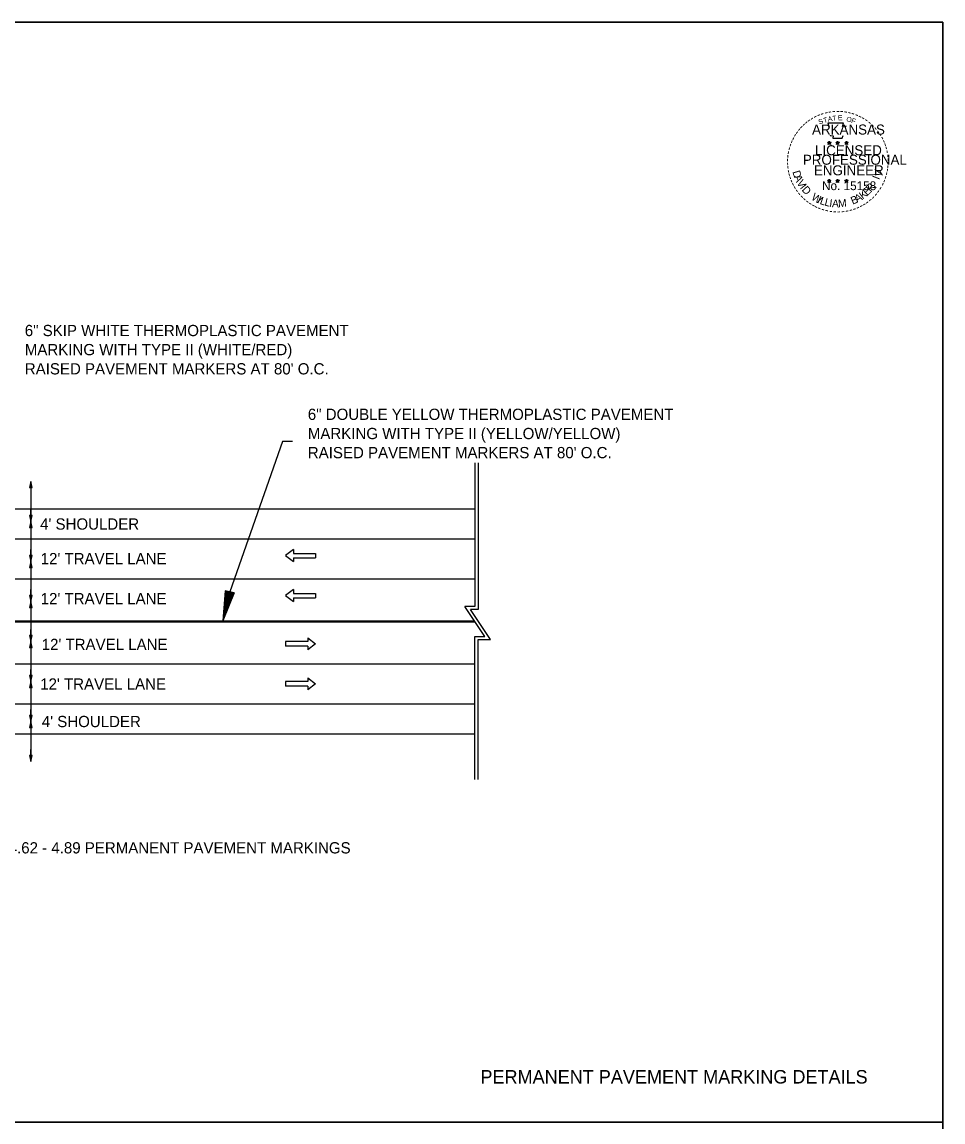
# Model space of a CAD drawing. Extents: x 1372926 to 1373096, y 381240 to 381790.
# Drawn here: x 1373003.9 to 1373096, y 381570.2 to 381680.2 of the extents above; entities that cross this region are included whole.
import ezdxf

# ---------------------------------------------------------------- set-up
doc = ezdxf.new("R2010")
doc.units = 0
for name, color, linetype in [('Default', 7, 'Continuous'), ('DSN_DRFT_Junk-No-Plot', 7, 'Continuous'), ('R_Border Notes', 7, 'Continuous'), ('R_Draft', 7, 'Continuous'), ('SHET_Border-Text', 7, 'Continuous')]:
    doc.layers.add(name, color=color, linetype=linetype)

msp = doc.modelspace()

# ---------------------------------------------------------------- linework, layer by layer
at = {"layer": 'Default'}
for p, q in [((1373029.94, 381638.21), (1373024.65, 381623.19)), ((1373030.94, 381638.21), (1373029.94, 381638.21)), ((1373049.17, 381636.08), (1373049.17, 381621.74)), ((1373049.5, 381636.08), (1373049.5, 381621.41)), ((1373031.02, 381627.41), (1373030.24, 381626.81)), ((1373031.02, 381627.41), (1373031.02, 381627.04)), ((1373030.24, 381626.81), (1373031.02, 381626.21)), ((1373031.02, 381627.04), (1373033.23, 381627.04)), ((1373031.02, 381626.59), (1373033.23, 381626.59)), ((1373031.02, 381626.59), (1373031.02, 381626.21)), ((1373033.23, 381627.04), (1373033.23, 381626.59)), ((1373024.21, 381623.3), (1373023.95, 381620.28)), ((1373025.09, 381623.09), (1373023.95, 381620.28)), ((1373024.29, 381623.28), (1373024.06, 381620.77)), ((1373025.01, 381623.11), (1373024.06, 381620.77)), ((1373024.36, 381623.26), (1373024.18, 381621.27)), ((1373024.94, 381623.12), (1373024.18, 381621.27)), ((1373025.09, 381623.09), (1373024.21, 381623.3)), ((1373024.43, 381623.25), (1373024.3, 381621.75)), ((1373024.87, 381623.14), (1373024.3, 381621.75)), ((1373024.51, 381623.23), (1373024.42, 381622.25)), ((1373024.79, 381623.16), (1373024.42, 381622.25)), ((1373024.58, 381623.21), (1373024.54, 381622.73)), ((1373024.72, 381623.18), (1373024.54, 381622.73)), ((1373031.02, 381623.41), (1373030.24, 381622.81)), ((1373031.02, 381623.41), (1373031.02, 381623.04)), ((1373031.02, 381623.04), (1373033.23, 381623.04)), ((1373033.23, 381623.04), (1373033.23, 381622.59)), ((1373030.24, 381622.81), (1373031.02, 381622.21)), ((1373031.02, 381622.59), (1373033.23, 381622.59)), ((1373031.02, 381622.59), (1373031.02, 381622.21)), ((1373049.17, 381621.74), (1373048.17, 381621.74)), ((1373050.17, 381618.74), (1373048.17, 381621.74)), ((1373050.72, 381618.41), (1373048.72, 381621.41)), ((1373049.5, 381621.41), (1373048.72, 381621.41)), ((1373049.17, 381604.41), (1373049.17, 381618.74)), ((1373049.17, 381618.74), (1373050.17, 381618.74)), ((1373032.45, 381618.22), (1373030.24, 381618.22)), ((1373030.24, 381618.22), (1373030.24, 381617.77)), ((1373032.45, 381617.77), (1373030.24, 381617.77)), ((1373032.45, 381618.59), (1373032.45, 381618.22)), ((1373032.45, 381618.59), (1373033.23, 381617.99)), ((1373033.23, 381617.99), (1373032.45, 381617.39)), ((1373032.45, 381617.77), (1373032.45, 381617.39)), ((1373049.5, 381604.41), (1373049.5, 381618.41)), ((1373049.5, 381618.41), (1373050.72, 381618.41)), ((1373032.45, 381614.22), (1373030.24, 381614.22)), ((1373030.24, 381614.22), (1373030.24, 381613.77)), ((1373032.45, 381614.59), (1373032.45, 381614.22)), ((1373032.45, 381614.59), (1373033.23, 381613.99)), ((1373032.45, 381613.77), (1373030.24, 381613.77)), ((1373033.23, 381613.99), (1373032.45, 381613.39)), ((1373032.45, 381613.77), (1373032.45, 381613.39))]:
    msp.add_line(p, q, dxfattribs=at)
for points in [[(1372925.97, 381680.17), (1372925.97, 381570.17), (1373095.97, 381570.17), (1373095.97, 381680.17)], [(1372925.97, 381570.17), (1372925.97, 381460.17), (1373095.97, 381460.17), (1373095.97, 381570.17)]]:
    msp.add_lwpolyline(points, close=True, dxfattribs=at)
at = {"layer": 'DSN_DRFT_Junk-No-Plot'}
msp.add_line((1373004.76, 381634.24), (1373004.76, 381606.24), dxfattribs=at)
for points in [[(1372925.97, 381680.17), (1373095.97, 381680.17), (1373095.97, 381570.17), (1372925.97, 381570.17)], [(1372925.97, 381680.17), (1372925.97, 381570.17), (1373095.97, 381570.17), (1373095.97, 381680.17)], [(1372925.97, 381570.17), (1373095.97, 381570.17), (1373095.97, 381460.17), (1372925.97, 381460.17)], [(1372925.97, 381570.17), (1372925.97, 381460.17), (1373095.97, 381460.17), (1373095.97, 381570.17)]]:
    msp.add_lwpolyline(points, close=True, dxfattribs=at)
for points in [[(1373004.76, 381634.24), (1373004.64, 381633.64), (1373004.88, 381633.64), (1373004.76, 381634.24), (1373004.76, 381633.04)], [(1373004.76, 381630.24), (1373004.88, 381630.84), (1373004.64, 381630.84), (1373004.76, 381630.24), (1373004.76, 381631.44)], [(1373004.76, 381630.24), (1373004.64, 381629.64), (1373004.88, 381629.64), (1373004.76, 381630.24), (1373004.76, 381629.04)], [(1373004.76, 381626.24), (1373004.88, 381626.84), (1373004.64, 381626.84), (1373004.76, 381626.24), (1373004.76, 381627.44)], [(1373004.76, 381626.24), (1373004.64, 381625.64), (1373004.88, 381625.64), (1373004.76, 381626.24), (1373004.76, 381625.04)], [(1373004.76, 381622.24), (1373004.88, 381622.84), (1373004.64, 381622.84), (1373004.76, 381622.24), (1373004.76, 381623.44)], [(1373004.76, 381622.24), (1373004.64, 381621.64), (1373004.88, 381621.64), (1373004.76, 381622.24), (1373004.76, 381621.04)], [(1373004.76, 381618.24), (1373004.88, 381618.84), (1373004.64, 381618.84), (1373004.76, 381618.24), (1373004.76, 381619.44)], [(1373004.76, 381618.24), (1373004.64, 381617.64), (1373004.88, 381617.64), (1373004.76, 381618.24), (1373004.76, 381617.04)], [(1373004.76, 381614.24), (1373004.88, 381614.84), (1373004.64, 381614.84), (1373004.76, 381614.24), (1373004.76, 381615.44)], [(1373004.76, 381614.24), (1373004.64, 381613.64), (1373004.88, 381613.64), (1373004.76, 381614.24), (1373004.76, 381613.04)], [(1373004.76, 381610.24), (1373004.88, 381610.84), (1373004.64, 381610.84), (1373004.76, 381610.24), (1373004.76, 381611.44)], [(1373004.76, 381610.24), (1373004.64, 381609.64), (1373004.88, 381609.64), (1373004.76, 381610.24), (1373004.76, 381609.04)], [(1373004.76, 381606.24), (1373004.88, 381606.84), (1373004.64, 381606.84), (1373004.76, 381606.24), (1373004.76, 381607.44)]]:
    msp.add_lwpolyline(points, dxfattribs=at)
at = {"layer": 'R_Draft'}
for p, q in [((1372972.78, 381631.49), (1373049.17, 381631.49)), ((1372972.78, 381628.49), (1373049.17, 381628.49)), ((1372972.78, 381624.49), (1373049.17, 381624.49)), ((1372972.74, 381620.29), (1373049.14, 381620.29)), ((1372972.81, 381620.19), (1373049.2, 381620.19)), ((1372972.78, 381615.99), (1373049.17, 381615.99)), ((1372972.78, 381611.99), (1373049.17, 381611.99)), ((1372972.78, 381608.99), (1373049.17, 381608.99))]:
    msp.add_line(p, q, dxfattribs=at)
at = {"layer": 'SHET_Border-Text'}
for p, q in [((1373084.43, 381668.13), (1373084.6, 381668.07)), ((1373084.43, 381668.13), (1373084.56, 381668.11)), ((1373084.43, 381668.13), (1373084.55, 381668.07)), ((1373084.6, 381668.26), (1373084.58, 381668.13)), ((1373084.6, 381668.07), (1373084.6, 381668.26)), ((1373084.6, 381668.26), (1373084.63, 381668.13)), ((1373084.78, 381668.13), (1373084.6, 381668.07)), ((1373084.78, 381668.13), (1373084.63, 381668.11)), ((1373084.78, 381668.13), (1373084.67, 381668.08)), ((1373085.26, 381668.13), (1373085.44, 381668.07)), ((1373085.26, 381668.13), (1373085.39, 381668.11)), ((1373085.26, 381668.13), (1373085.38, 381668.07)), ((1373085.44, 381668.26), (1373085.42, 381668.13)), ((1373085.44, 381668.07), (1373085.44, 381668.26)), ((1373085.44, 381668.26), (1373085.46, 381668.13)), ((1373085.61, 381668.13), (1373085.44, 381668.07)), ((1373085.61, 381668.13), (1373085.47, 381668.11)), ((1373085.61, 381668.13), (1373085.51, 381668.08)), ((1373086.15, 381668.12), (1373086.32, 381668.07)), ((1373086.15, 381668.12), (1373086.27, 381668.1)), ((1373086.15, 381668.12), (1373086.26, 381668.06)), ((1373086.32, 381668.25), (1373086.3, 381668.12)), ((1373086.32, 381668.07), (1373086.32, 381668.25)), ((1373086.32, 381668.25), (1373086.34, 381668.13)), ((1373086.49, 381668.12), (1373086.32, 381668.07)), ((1373086.49, 381668.12), (1373086.35, 381668.1)), ((1373086.49, 381668.12), (1373086.39, 381668.07)), ((1373084.5, 381667.93), (1373084.6, 381668.07)), ((1373084.5, 381667.93), (1373084.56, 381668.05)), ((1373084.5, 381667.93), (1373084.6, 381668.03)), ((1373084.71, 381667.93), (1373084.6, 381668.07)), ((1373084.71, 381667.93), (1373084.6, 381668.03)), ((1373084.71, 381667.93), (1373084.64, 381668.07)), ((1373085.33, 381667.93), (1373085.44, 381668.07)), ((1373085.33, 381667.93), (1373085.39, 381668.05)), ((1373085.33, 381667.93), (1373085.44, 381668.03)), ((1373085.54, 381667.93), (1373085.44, 381668.07)), ((1373085.54, 381667.93), (1373085.44, 381668.03)), ((1373085.54, 381667.93), (1373085.48, 381668.07)), ((1373086.21, 381667.92), (1373086.32, 381668.07)), ((1373086.21, 381667.92), (1373086.28, 381668.04)), ((1373086.21, 381667.92), (1373086.32, 381668.03)), ((1373086.43, 381667.92), (1373086.32, 381668.07)), ((1373086.43, 381667.92), (1373086.32, 381668.03)), ((1373086.43, 381667.92), (1373086.36, 381668.07)), ((1373084.43, 381664.34), (1373084.6, 381664.29)), ((1373084.43, 381664.34), (1373084.55, 381664.32)), ((1373084.43, 381664.34), (1373084.55, 381664.28)), ((1373084.49, 381664.14), (1373084.6, 381664.29)), ((1373084.49, 381664.14), (1373084.56, 381664.26)), ((1373084.49, 381664.14), (1373084.6, 381664.25)), ((1373084.6, 381664.47), (1373084.58, 381664.34)), ((1373084.6, 381664.29), (1373084.6, 381664.47)), ((1373084.6, 381664.47), (1373084.63, 381664.35)), ((1373084.77, 381664.34), (1373084.6, 381664.29)), ((1373084.71, 381664.14), (1373084.6, 381664.29)), ((1373084.71, 381664.14), (1373084.6, 381664.25)), ((1373084.77, 381664.34), (1373084.63, 381664.32)), ((1373084.71, 381664.14), (1373084.64, 381664.28)), ((1373084.77, 381664.34), (1373084.67, 381664.29)), ((1373085.26, 381664.34), (1373085.44, 381664.29)), ((1373085.26, 381664.34), (1373085.39, 381664.32)), ((1373085.26, 381664.34), (1373085.38, 381664.28)), ((1373085.33, 381664.14), (1373085.44, 381664.29)), ((1373085.33, 381664.14), (1373085.39, 381664.26)), ((1373085.33, 381664.14), (1373085.43, 381664.25)), ((1373085.44, 381664.47), (1373085.42, 381664.34)), ((1373085.54, 381664.14), (1373085.43, 381664.25)), ((1373085.44, 381664.29), (1373085.44, 381664.47)), ((1373085.44, 381664.47), (1373085.46, 381664.35)), ((1373085.61, 381664.34), (1373085.44, 381664.29)), ((1373085.54, 381664.14), (1373085.44, 381664.29)), ((1373085.61, 381664.34), (1373085.47, 381664.32)), ((1373085.54, 381664.14), (1373085.47, 381664.28)), ((1373085.61, 381664.34), (1373085.51, 381664.29)), ((1373086.14, 381664.34), (1373086.32, 381664.28)), ((1373086.14, 381664.34), (1373086.27, 381664.32)), ((1373086.14, 381664.34), (1373086.26, 381664.28)), ((1373086.21, 381664.13), (1373086.32, 381664.28)), ((1373086.21, 381664.13), (1373086.27, 381664.26)), ((1373086.21, 381664.13), (1373086.32, 381664.24)), ((1373086.32, 381664.47), (1373086.3, 381664.34)), ((1373086.32, 381664.28), (1373086.32, 381664.47)), ((1373086.32, 381664.47), (1373086.34, 381664.34)), ((1373086.49, 381664.34), (1373086.32, 381664.28)), ((1373086.43, 381664.13), (1373086.32, 381664.28)), ((1373086.43, 381664.13), (1373086.32, 381664.24)), ((1373086.49, 381664.34), (1373086.35, 381664.31)), ((1373086.43, 381664.13), (1373086.36, 381664.28)), ((1373086.49, 381664.34), (1373086.39, 381664.29))]:
    msp.add_line(p, q, dxfattribs=at)
for points in [[(1373084.45, 381670.07), (1373084.58, 381669.66)], [(1373086.2, 381669.61), (1373086.28, 381669.75), (1373085.93, 381669.74), (1373086.01, 381670.07), (1373084.45, 381670.07)], [(1373084.6, 381668.26), (1373084.71, 381667.93), (1373084.43, 381668.13), (1373084.78, 381668.13), (1373084.5, 381667.93), (1373084.6, 381668.26)], [(1373084.7, 381668.86), (1373084.7, 381668.81), (1373084.98, 381668.8), (1373084.95, 381668.57), (1373085.88, 381668.57), (1373085.99, 381668.84)], [(1373085.44, 381668.26), (1373085.54, 381667.93), (1373085.26, 381668.13), (1373085.61, 381668.13), (1373085.33, 381667.93), (1373085.44, 381668.26)], [(1373086.32, 381668.25), (1373086.43, 381667.92), (1373086.15, 381668.12), (1373086.49, 381668.12), (1373086.21, 381667.92), (1373086.32, 381668.25)], [(1373084.6, 381664.47), (1373084.71, 381664.14), (1373084.43, 381664.34), (1373084.77, 381664.34), (1373084.49, 381664.14), (1373084.6, 381664.47)], [(1373085.44, 381664.47), (1373085.54, 381664.14), (1373085.26, 381664.34), (1373085.61, 381664.34), (1373085.33, 381664.14), (1373085.44, 381664.47)], [(1373086.32, 381664.47), (1373086.43, 381664.13), (1373086.14, 381664.34), (1373086.49, 381664.34), (1373086.21, 381664.13), (1373086.32, 381664.47)]]:
    msp.add_lwpolyline(points, dxfattribs=at)
for centre, radius in [((1373084.6, 381668.07), 0.0861), ((1373084.6, 381668.07), 0.0723), ((1373084.6, 381668.07), 0.0579), ((1373084.6, 381668.07), 0.0495), ((1373084.6, 381668.07), 0.0374), ((1373085.44, 381668.07), 0.0861), ((1373085.44, 381668.07), 0.0723), ((1373085.44, 381668.07), 0.0579), ((1373085.44, 381668.07), 0.0495), ((1373085.44, 381668.07), 0.0374), ((1373086.32, 381668.07), 0.0861), ((1373086.32, 381668.07), 0.0723), ((1373086.32, 381668.07), 0.0579), ((1373086.32, 381668.07), 0.0495), ((1373086.32, 381668.07), 0.0374), ((1373084.6, 381668.07), 0.0248), ((1373084.6, 381668.07), 0.0148), ((1373085.44, 381668.07), 0.0248), ((1373085.44, 381668.07), 0.0148), ((1373086.32, 381668.07), 0.0248), ((1373086.32, 381668.07), 0.0148), ((1373084.6, 381664.29), 0.0861), ((1373084.6, 381664.29), 0.0723), ((1373084.6, 381664.29), 0.0579), ((1373084.6, 381664.29), 0.0495), ((1373084.6, 381664.29), 0.0374), ((1373084.6, 381664.29), 0.0248), ((1373084.6, 381664.29), 0.0148), ((1373085.44, 381664.29), 0.0861), ((1373085.44, 381664.29), 0.0723), ((1373085.44, 381664.29), 0.0579), ((1373085.44, 381664.29), 0.0495), ((1373085.44, 381664.29), 0.0374), ((1373085.44, 381664.29), 0.0248), ((1373085.44, 381664.29), 0.0148), ((1373086.32, 381664.28), 0.0861), ((1373086.32, 381664.28), 0.0723), ((1373086.32, 381664.28), 0.0579), ((1373086.32, 381664.28), 0.0495), ((1373086.32, 381664.28), 0.0374), ((1373086.32, 381664.28), 0.0248), ((1373086.32, 381664.28), 0.0148)]:
    msp.add_circle(centre, radius, dxfattribs=at)

# ---------------------------------------------------------------- texts
at = {"layer": 'Default'}
for s, p in [('6" SKIP WHITE THERMOPLASTIC PAVEMENT', (1373004.16, 381648.76)), ('MARKING WITH TYPE II (WHITE/RED)', (1373004.16, 381646.85)), ("RAISED PAVEMENT MARKERS AT 80' O.C.", (1373004.16, 381644.93)), ('6" DOUBLE YELLOW THERMOPLASTIC PAVEMENT', (1373032.46, 381640.38)), ('MARKING WITH TYPE II (YELLOW/YELLOW)', (1373032.46, 381638.46)), ("RAISED PAVEMENT MARKERS AT 80' O.C.", (1373032.46, 381636.55))]:
    msp.add_text(s, height=1.125, dxfattribs=at).set_placement(p)
at = {"layer": 'R_Border Notes'}
msp.add_text('PERMANENT PAVEMENT MARKING DETAILS', height=1.35, dxfattribs=at).set_placement((1373049.72, 381574.02))
at = {"layer": 'R_Draft'}
for s, p in [("4' SHOULDER", (1373005.69, 381629.41)), ("12' TRAVEL LANE", (1373005.75, 381625.95)), ("12' TRAVEL LANE", (1373005.75, 381621.95)), ("12' TRAVEL LANE", (1373005.85, 381617.37)), ("12' TRAVEL LANE", (1373005.7, 381613.41)), ("4' SHOULDER", (1373005.86, 381609.66)), ('HWY. 67, SECTION 8 L.M. 4.62 - 4.89 PERMANENT PAVEMENT MARKINGS', (1372983.99, 381597.03))]:
    msp.add_text(s, height=1.125, dxfattribs=at).set_placement(p)
at = {"layer": 'SHET_Border-Text'}
for s, height, rotation, p in [('-', 0.8, 36.2317, (1373082.6, 381669.96)), ('-', 0.8, 34.0636, (1373082.89, 381670.15)), ('-', 0.8, 28.7918, (1373083.19, 381670.34)), ('-', 0.8, 24.3072, (1373083.51, 381670.5)), ('S', 0.5, 21.594, (1373083.63, 381669.91)), ('-', 0.8, 19.1761, (1373083.82, 381670.63)), ('T', 0.5, 16.4036, (1373084.08, 381670.07)), ('-', 0.8, 13.6302, (1373084.2, 381670.75)), ('A', 0.5, 11.2132, (1373084.5, 381670.2)), ('-', 0.8, 10.2193, (1373084.54, 381670.83)), ('T', 0.5, 6.0228, (1373084.92, 381670.28)), ('-', 0.8, 5.8968, (1373084.9, 381670.89)), ('-', 0.8, 0.1862, (1373085.29, 381670.92)), ('E', 0.5, 0.8323, (1373085.47, 381670.34)), ('-', 0.8, 357.743, (1373085.65, 381670.92)), ('-', 0.8, 352.1617, (1373086.02, 381670.89)), ('O', 0.5, 350.4515, (1373086.28, 381670.23)), ('-', 0.8, 347.2049, (1373086.38, 381670.83)), ('F', 0.5, 340.0707, (1373086.75, 381670.12)), ('-', 0.8, 342.3362, (1373086.7, 381670.76)), ('-', 0.8, 337.8551, (1373087.07, 381670.64)), ('-', 0.8, 334.1211, (1373087.38, 381670.51)), ('-', 0.8, 329.6409, (1373087.67, 381670.37)), ('-', 0.8, 325.8627, (1373087.99, 381670.19)), ('-', 0.8, 54.2325, (1373081.52, 381668.79)), ('-', 0.8, 50.6142, (1373081.72, 381669.08)), ('-', 0.8, 48.4231, (1373081.92, 381669.32)), ('-', 0.8, 42.9622, (1373082.15, 381669.56)), ('-', 0.8, 38.9507, (1373082.36, 381669.77)), ('-', 0.8, 320.5297, (1373088.3, 381669.97)), ('-', 0.8, 315.5786, (1373088.6, 381669.73)), ('-', 0.8, 309.8797, (1373088.88, 381669.45)), ('-', 0.8, 306.6522, (1373089.14, 381669.15)), ('-', 0.8, 67.7743, (1373081.07, 381667.92)), ('-', 0.8, 62.8713, (1373081.2, 381668.22)), ('-', 0.8, 58.0706, (1373081.35, 381668.53)), ('-', 0.7, 303.6753, (1373089.39, 381668.87)), ('-', 0.8, 299.6684, (1373089.55, 381668.57)), ('-', 0.8, 294.6628, (1373089.71, 381668.26)), ('-', 0.8, 81.2013, (1373080.79, 381666.89)), ('-', 0.8, 75.461, (1373080.86, 381667.25)), ('-', 0.8, 72.3945, (1373080.96, 381667.6)), ('-', 0.8, 290.5728, (1373089.84, 381667.97)), ('-', 0.8, 285.1233, (1373089.95, 381667.68)), ('-', 0.8, 280.5493, (1373090.05, 381667.31)), ('-', 0.8, 94.1959, (1373080.76, 381665.83)), ('-', 0.8, 89.0622, (1373080.74, 381666.19)), ('-', 0.8, 85.1863, (1373080.75, 381666.54)), ('-', 0.8, 276.5962, (1373090.13, 381666.93)), ('-', 0.8, 274.3301, (1373090.16, 381666.57)), ('-', 0.8, 269.9407, (1373090.18, 381666.25)), ('-', 0.8, 98.9479, (1373080.8, 381665.5)), ('-', 0.8, 101.7149, (1373080.86, 381665.13)), ('-', 0.8, 105.4578, (1373080.94, 381664.83)), ('D', 0.77, 286.2848, (1373080.91, 381665.2)), ('I', 0.77, 69.0301, (1373089.59, 381664.35)), ('V', 0.77, 72.6573, (1373089.7, 381664.62)), ('-', 0.8, 255.7626, (1373090.08, 381665.25)), ('-', 0.8, 260.9953, (1373090.14, 381665.59)), ('-', 0.8, 263.5172, (1373090.17, 381665.92)), ('-', 0.8, 109.0874, (1373081.05, 381664.52)), ('-', 0.8, 114.0643, (1373081.18, 381664.22)), ('-', 0.8, 115.7289, (1373081.33, 381663.91)), ('-', 0.8, 120.4471, (1373081.51, 381663.62)), ('A', 0.77, 292.7835, (1373081.05, 381664.7)), ('V', 0.77, 300.7936, (1373081.31, 381664.11)), ('I', 0.77, 308.3502, (1373081.63, 381663.59)), ('D', 0.77, 311.9774, (1373081.8, 381663.36)), ('E', 0.77, 44.0175, (1373088.4, 381662.75)), ('R', 0.77, 50.3651, (1373088.77, 381663.11)), (',', 0.77, 57.4684, (1373089.13, 381663.55)), ('-', 0.8, 244.6197, (1373089.75, 381664.24)), ('-', 0.8, 247.8887, (1373089.88, 381664.55)), ('-', 0.8, 252.8681, (1373089.99, 381664.89)), ('-', 0.8, 125.8934, (1373081.71, 381663.34)), ('-', 0.8, 130.7181, (1373081.94, 381663.06)), ('-', 0.8, 134.2238, (1373082.2, 381662.79)), ('W', 0.77, 328.0731, (1373082.74, 381662.47)), ('I', 0.77, 336.6877, (1373083.33, 381662.12)), ('L', 0.77, 340.3149, (1373083.6, 381662)), ('B', 0.77, 22.8589, (1373086.94, 381661.9)), ('A', 0.77, 28.9042, (1373087.39, 381662.09)), ('K', 0.77, 36.9143, (1373087.95, 381662.41)), ('-', 0.8, 225.7653, (1373088.9, 381662.97)), ('-', 0.8, 231.2538, (1373089.14, 381663.25)), ('-', 0.8, 233.8452, (1373089.35, 381663.54)), ('-', 0.8, 239.0712, (1373089.55, 381663.86)), ('-', 0.8, 138.9338, (1373082.46, 381662.56)), ('-', 0.8, 144.6463, (1373082.74, 381662.35)), ('-', 0.8, 148.0898, (1373083.02, 381662.17)), ('-', 0.8, 151.5704, (1373083.31, 381662.01)), ('-', 0.8, 154.6002, (1373083.57, 381661.88)), ('-', 0.8, 158.5612, (1373083.88, 381661.76)), ('L', 0.77, 346.6625, (1373084.08, 381661.83)), ('I', 0.77, 353.0101, (1373084.58, 381661.71)), ('A', 0.77, 356.6373, (1373084.86, 381661.66)), ('M', 0.77, 4.6473, (1373085.51, 381661.64)), ('-', 0.8, 199.4643, (1373087.19, 381661.82)), ('-', 0.8, 204.2516, (1373087.5, 381661.96)), ('-', 0.8, 207.3568, (1373087.81, 381662.12)), ('-', 0.8, 212.2491, (1373088.09, 381662.29)), ('-', 0.8, 215.7363, (1373088.36, 381662.48)), ('-', 0.8, 221.0851, (1373088.63, 381662.72)), ('-', 0.8, 162.7983, (1373084.23, 381661.65)), ('-', 0.8, 167.5555, (1373084.59, 381661.57)), ('-', 0.8, 173.1155, (1373084.97, 381661.51)), ('-', 0.8, 176.5183, (1373085.35, 381661.49)), ('-', 0.8, 181.5918, (1373085.72, 381661.49)), ('-', 0.8, 185.8167, (1373086.12, 381661.53)), ('-', 0.8, 191.2858, (1373086.49, 381661.6)), ('-', 0.8, 195.4743, (1373086.85, 381661.7))]:
    msp.add_text(s, height=height, rotation=rotation, dxfattribs=at).set_placement(p)
for s, height, p in [('ARKANSAS', 1, (1373082.88, 381668.92)), ('LICENSED', 1, (1373083.17, 381666.85)), ('PROFESSIONAL', 1, (1373081.96, 381665.9)), ('ENGINEER', 1, (1373083.06, 381664.84)), ('No. 15158', 0.878, (1373083.88, 381663.36)), ('AAMU', 0.00001, (1373085.4, 381661.63))]:
    msp.add_text(s, height=height, dxfattribs=at).set_placement(p)

doc.saveas('drawing.dxf')
